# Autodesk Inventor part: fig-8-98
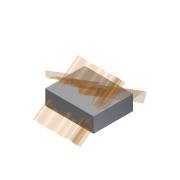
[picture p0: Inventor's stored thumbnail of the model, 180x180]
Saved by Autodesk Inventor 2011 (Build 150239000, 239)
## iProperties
Shininess: 64.0
Length Units: 11269
Angle Units: 11279
Time Units: 11290
Mass Units: 11283
Length Display Precision: 3
Angle Display Precision: 2
Compacted: True
Part Number: fig-8-98
Document SubType Name: Modeling
Created: 2002-12
Designer: deepak
Density: 1 g/cm^3
Density: 0.0
Volumn: 0.0
Area: 0.0
PropertySet Name: Model Information
Control State: 0
Master: False
Checked Out: False
Author: deepak
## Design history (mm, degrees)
sketch "Sketch1"
  geometry: L1 (-33.715, 26.527)-(30.916, 26.527); L2 (30.916, 26.527)-(30.916, -25.891); L3 (30.916, -25.891)-(-33.715, -25.891); L4 (-33.715, -25.891)-(-33.715, 26.527)
  constraints: 8 end point, 2 parallel, 1 horizontal, 1 perpendicular
extrude "Extrusion1" new body sketch "Sketch1" distance "d0" = 20; taper "d1" = 0 deg
sketch "Sketch2"
  geometry: L1 (-44.187, -5.757)-(15.849, 38.63)
  constraints: 2 end point
workplane "Work Plane1"
sketch "Sketch3"
  geometry: L1 (33.715, -6.248)-(33.715, 9.834) reference; L2 (-30.916, -6.248)-(-30.916, 9.834) reference; 10 further points
  constraints: 2 point on line, 11 other
feature "SweepSrf1" sketch "Sketch3" dims "d2" = 0
sketch "Sketch4"
  geometry: L1 (-26.819, 39.395)-(38.245, -1.181)
  constraints: 2 end point
workplane "Work Plane2"
sketch "Sketch5"
  geometry: L1 (-30.916, -5.198)-(-30.916, 11.772) reference; L2 (33.715, -5.198)-(33.715, 11.772) reference; 10 further points
  constraints: 2 point on line, 10 other
feature "SweepSrf2" sketch "Sketch5" dims "d3" = 0
body "Solid1"
body "Srf1"
body "Srf2"
